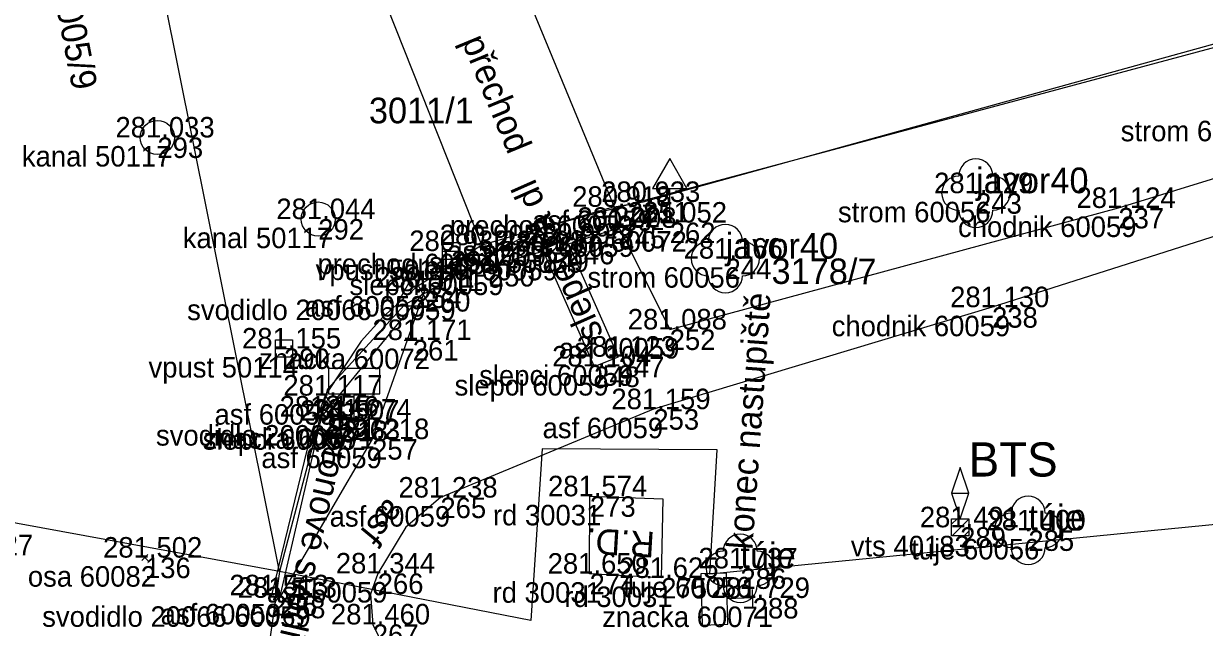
# Model space of a CAD drawing. Extents: x -728659 to -728362, y -1073110 to -1072943.
# Drawn here: x -728508.67 to -728474.14, y -1073039.57 to -1073021.92 of the extents above; entities that cross this region are included whole.
import ezdxf

# ---------------------------------------------------------------- set-up
doc = ezdxf.new("R2010")
doc.units = 0
for name, color, linetype in [('Vrstva 17', 7, 'Continuous'), ('Vrstva 23', 7, 'Continuous'), ('Vrstva 33', 7, 'Continuous'), ('Vrstva 43', 7, 'Continuous'), ('Vrstva 49', 7, 'Continuous'), ('Vrstva 50', 7, 'Continuous'), ('Vrstva 51', 7, 'Continuous'), ('Vrstva 53', 7, 'Continuous'), ('Vrstva 55', 7, 'Continuous'), ('Vrstva 57', 7, 'Continuous'), ('Vrstva 60', 7, 'Continuous'), ('Vrstva 61', 7, 'Continuous'), ('Vrstva 62', 7, 'Continuous'), ('Vrstva 63', 7, 'Continuous')]:
    doc.layers.add(name, color=color, linetype=linetype)

msp = doc.modelspace()

# ---------------------------------------------------------------- linework, layer by layer
at = {"layer": 'Vrstva 17'}
msp.add_lwpolyline([(-728496.944, -1073029.737), (-728499.959, -1073033.406), (-728501.183, -1073038.706)], dxfattribs=at)
at = {"layer": 'Vrstva 23'}
msp.add_lwpolyline([(-728490.023, -1073038.127), (-728492.121, -1073038.002), (-728492.11, -1073035.739), (-728489.978, -1073035.812), (-728490.023, -1073038.127)], dxfattribs=at)
at = {"layer": 'Vrstva 33'}
for p, q in [((-728481.532, -1073035.645), (-728481.032, -1073035.645)), ((-728481.532, -1073036.553), (-728481.374, -1073036.395)), ((-728481.52, -1073036.895), (-728481.032, -1073036.407)), ((-728481.167, -1073036.895), (-728481.032, -1073036.76))]:
    msp.add_line(p, q, dxfattribs=at)
msp.add_lwpolyline([(-728481.282, -1073034.895), (-728481.532, -1073035.645), (-728481.282, -1073036.395), (-728481.032, -1073035.645), (-728481.282, -1073034.895)], dxfattribs=at)
msp.add_lwpolyline([(-728481.532, -1073036.395), (-728481.032, -1073036.395), (-728481.032, -1073036.895), (-728481.532, -1073036.895)], close=True, dxfattribs=at)
at = {"layer": 'Vrstva 43'}
for points in [[(-728496.418, -1073028.566), (-728496.418, -1073028.316), (-728495.918, -1073028.316), (-728495.918, -1073028.816), (-728496.418, -1073028.816), (-728496.418, -1073028.566), (-728495.918, -1073028.566)], [(-728501.306, -1073031.416), (-728501.306, -1073031.166), (-728500.806, -1073031.166), (-728500.806, -1073031.666), (-728501.306, -1073031.666), (-728501.306, -1073031.416), (-728500.806, -1073031.416)]]:
    msp.add_lwpolyline(points, dxfattribs=at)
for centre in [(-728504.759, -1073025.245), (-728500.055, -1073027.632)]:
    msp.add_circle(centre, 0.5, dxfattribs=at)
at = {"layer": 'Vrstva 49'}
for p, q in [((-728505.035, -1073037.62), (-728505.211, -1073037.444)), ((-728505.035, -1073037.444), (-728505.211, -1073037.62))]:
    msp.add_line(p, q, dxfattribs=at)
at = {"layer": 'Vrstva 50'}
for p, q in [((-728480.853, -1073026.875), (-728480.782, -1073026.875)), ((-728488.179, -1073028.788), (-728488.108, -1073028.788)), ((-728479.323, -1073036.736), (-728479.252, -1073036.736)), ((-728487.743, -1073037.847), (-728487.672, -1073037.847))]:
    msp.add_line(p, q, dxfattribs=at)
for centre, start, end in [((-728480.823, -1073026.374), 0, 180), ((-728481.323, -1073026.874), 90, 270), ((-728480.323, -1073026.874), 270, 90), ((-728480.823, -1073027.374), 180, 0), ((-728488.149, -1073028.287), 0, 180), ((-728488.649, -1073028.787), 90, 270), ((-728487.649, -1073028.787), 270, 90), ((-728488.149, -1073029.287), 180, 0), ((-728479.292, -1073036.235), 0, 180), ((-728479.792, -1073036.735), 90, 270), ((-728478.792, -1073036.735), 270, 90), ((-728487.714, -1073037.346), 0, 180), ((-728488.214, -1073037.846), 90, 270), ((-728487.214, -1073037.846), 270, 90), ((-728479.292, -1073037.235), 180, 0), ((-728487.714, -1073038.346), 180, 0)]:
    msp.add_arc(centre, 0.5, start, end, dxfattribs=at)
at = {"layer": 'Vrstva 51'}
for p, q in [((-728490.027, -1073027.735), (-728489.527, -1073027.735)), ((-728497.54, -1073031.169), (-728497.04, -1073031.169)), ((-728499.25, -1073033.497), (-728498.75, -1073033.497)), ((-728487.341, -1073038.963), (-728487.355, -1073038.463))]:
    msp.add_line(p, q, dxfattribs=at)
for points in [[(-728491.401, -1073027.273), (-728490.555, -1073027.131), (-728438.49, -1073012.708)], [(-728491.25, -1073027.888), (-728489.777, -1073030.86), (-728476.655, -1073027.306), (-728450.209, -1073019.139)], [(-728498.56, -1073020.107), (-728494.628, -1073019.466), (-728491.401, -1073027.273), (-728495.275, -1073028.394), (-728498.56, -1073020.107)], [(-728449.745, -1073020.446), (-728480.35, -1073030.208), (-728490.255, -1073033.191), (-728496.482, -1073035.776)], [(-728489.777, -1073027.735), (-728489.777, -1073026.735), (-728489.277, -1073026.735), (-728489.777, -1073025.86), (-728490.277, -1073026.735), (-728489.777, -1073026.735)], [(-728495.275, -1073028.394), (-728495.063, -1073029.004), (-728493.479, -1073028.573), (-728491.99, -1073031.943), (-728491.271, -1073031.657), (-728492.733, -1073028.355), (-728491.25, -1073027.888), (-728491.401, -1073027.273)], [(-728495.275, -1073028.394), (-728497.204, -1073029.633), (-728498.169, -1073030.501), (-728498.796, -1073031.198), (-728499.849, -1073032.794), (-728500.268, -1073033.914), (-728501.425, -1073038.634)], [(-728497.29, -1073031.169), (-728497.29, -1073030.169), (-728496.79, -1073030.169), (-728497.29, -1073029.294), (-728497.79, -1073030.169), (-728497.29, -1073030.169)], [(-728496.944, -1073029.737), (-728498.48, -1073034.066), (-728501.183, -1073038.706)], [(-728499, -1073033.497), (-728499, -1073032.747), (-728498.25, -1073032.747), (-728498.25, -1073031.997), (-728499.75, -1073031.997), (-728499.75, -1073032.747), (-728499, -1073032.747)], [(-728499.849, -1073032.794), (-728499.355, -1073033.527)], [(-728496.482, -1073035.776), (-728497.494, -1073036.644), (-728498.316, -1073037.996), (-728498.528, -1073038.603), (-728498.459, -1073039.486), (-728498.149, -1073040.128), (-728497.533, -1073040.603), (-728496.825, -1073040.892), (-728494.827, -1073041.079), (-728486.835, -1073041.479), (-728486.937, -1073042.858), (-728494.923, -1073042.391), (-728498.977, -1073042.014), (-728499.069, -1073042.727), (-728513.553, -1073040.642)], [(-728487.348, -1073038.713), (-728488.098, -1073038.733), (-728488.118, -1073037.983), (-728488.867, -1073038.003), (-728488.827, -1073039.503), (-728488.078, -1073039.483), (-728488.098, -1073038.733)]]:
    msp.add_lwpolyline(points, dxfattribs=at)
at = {"layer": 'Vrstva 53'}
msp.add_lwpolyline([(-728443.68, -1073014.51), (-728493.68, -1073027.94), (-728497.54, -1073030.15), (-728499.78, -1073032.61), (-728501.19, -1073037.94), (-728503.24, -1073052.34), (-728496.81, -1073052.21), (-728491.97, -1073053.44), (-728477.97, -1073053.19), (-728434.587, -1073049.291), (-728361.73, -1073039.5)], dxfattribs=at)
at = {"layer": 'Vrstva 55'}
for q in [(-728506.11, -1073013.42), (-728510.22, -1073036.28)]:
    msp.add_line((-728501.19, -1073037.94), q, dxfattribs=at)
msp.add_lwpolyline([(-728462.29, -1073035.43), (-728488.6, -1073038.02), (-728488.39, -1073034.38), (-728493.51, -1073034.35), (-728493.84, -1073039.37), (-728501.19, -1073037.94)], dxfattribs=at)
at = {"layer": 'Vrstva 60'}
for p, q in [((-728504.759, -1073025.245), (-728504.759, -1073025.245)), ((-728490.555, -1073027.131), (-728490.555, -1073027.131)), ((-728480.817, -1073026.875), (-728480.817, -1073026.875)), ((-728491.401, -1073027.273), (-728491.401, -1073027.273)), ((-728476.655, -1073027.306), (-728476.655, -1073027.306)), ((-728500.055, -1073027.632), (-728500.055, -1073027.632)), ((-728489.777, -1073027.735), (-728489.777, -1073027.735)), ((-728491.25, -1073027.888), (-728491.25, -1073027.888)), ((-728496.168, -1073028.566), (-728496.168, -1073028.566)), ((-728495.275, -1073028.394), (-728495.275, -1073028.394)), ((-728492.733, -1073028.355), (-728492.733, -1073028.355)), ((-728493.479, -1073028.573), (-728493.479, -1073028.573)), ((-728488.143, -1073028.788), (-728488.143, -1073028.788)), ((-728495.063, -1073029.004), (-728495.063, -1073029.004)), ((-728497.204, -1073029.633), (-728497.204, -1073029.633)), ((-728496.944, -1073029.737), (-728496.944, -1073029.737)), ((-728480.35, -1073030.208), (-728480.35, -1073030.208)), ((-728489.777, -1073030.86), (-728489.777, -1073030.86)), ((-728497.29, -1073031.169), (-728497.29, -1073031.169)), ((-728501.056, -1073031.416), (-728501.056, -1073031.416)), ((-728491.271, -1073031.657), (-728491.271, -1073031.657)), ((-728491.99, -1073031.943), (-728491.99, -1073031.943)), ((-728499.849, -1073032.794), (-728499.849, -1073032.794)), ((-728490.255, -1073033.191), (-728490.255, -1073033.191)), ((-728499.959, -1073033.406), (-728499.959, -1073033.406)), ((-728499.355, -1073033.527), (-728499.355, -1073033.527)), ((-728499, -1073033.497), (-728499, -1073033.497)), ((-728498.48, -1073034.066), (-728498.48, -1073034.066)), ((-728496.482, -1073035.776), (-728496.482, -1073035.776)), ((-728492.11, -1073035.739), (-728492.11, -1073035.739)), ((-728481.282, -1073036.645), (-728481.282, -1073036.645)), ((-728479.287, -1073036.736), (-728479.287, -1073036.736)), ((-728505.123, -1073037.532), (-728505.123, -1073037.532)), ((-728487.708, -1073037.847), (-728487.708, -1073037.847)), ((-728498.316, -1073037.996), (-728498.316, -1073037.996)), ((-728492.121, -1073038.002), (-728492.121, -1073038.002)), ((-728490.023, -1073038.127), (-728490.023, -1073038.127)), ((-728501.425, -1073038.634), (-728501.425, -1073038.634)), ((-728501.183, -1073038.706), (-728501.183, -1073038.706)), ((-728487.348, -1073038.713), (-728487.348, -1073038.713)), ((-728498.459, -1073039.486), (-728498.459, -1073039.486))]:
    msp.add_line(p, q, dxfattribs=at)

# ---------------------------------------------------------------- texts
at = {"layer": 'Vrstva 23'}
msp.add_text('R.D.', height=0.75, rotation=176.5903, dxfattribs=at).set_placement((-728490.194, -1073036.786))
at = {"layer": 'Vrstva 33'}
msp.add_text('BTS', height=1, dxfattribs=at).set_placement((-728481.032, -1073035.161))
at = {"layer": 'Vrstva 51'}
for s, rotation, p in [('přechod', 292.4576, (-728495.874, -1073022.428)), ('slepecká dl ', 113.8819, (-728491.704, -1073031.002)), ('asf', 230.439, (-728498.024, -1073035.754))]:
    msp.add_text(s, height=0.75, rotation=rotation, dxfattribs=at).set_placement(p)
at = {"layer": 'Vrstva 57'}
for s, rotation, p in [('3005/9', 280.9963, (-728507.822, -1073020.889)), ('3178/7', 359.7358, (-728486.799, -1073029.526))]:
    msp.add_text(s, height=0.75, rotation=rotation, dxfattribs=at).set_placement(p)
msp.add_text('3011/1', height=0.75, dxfattribs=at).set_placement((-728498.572, -1073024.831))
at = {"layer": 'Vrstva 60'}
for s, p in [('293', (-728504.759, -1073025.845)), ('251', (-728490.555, -1073027.731)), ('243', (-728480.817, -1073027.475)), ('222', (-728491.401, -1073027.873)), ('237', (-728476.655, -1073027.906)), ('292', (-728500.055, -1073028.232)), ('245', (-728491.25, -1073028.488)), ('262', (-728489.777, -1073028.335)), ('291', (-728496.168, -1073029.166)), ('223', (-728495.275, -1073028.994)), ('249', (-728493.479, -1073029.173)), ('246', (-728492.733, -1073028.955)), ('244', (-728488.143, -1073029.388)), ('250', (-728495.063, -1073029.604)), ('254', (-728497.204, -1073030.233)), ('260', (-728496.944, -1073030.337)), ('238', (-728480.35, -1073030.808)), ('252', (-728489.777, -1073031.46)), ('261', (-728497.29, -1073031.769)), ('290', (-728501.056, -1073032.016)), ('247', (-728491.271, -1073032.257)), ('248', (-728491.99, -1073032.543)), ('255', (-728499.849, -1073033.394)), ('259', (-728499.959, -1073034.006)), ('253', (-728490.255, -1073033.791)), ('218', (-728499.355, -1073034.127)), ('263', (-728499, -1073034.097)), ('257', (-728498.48, -1073034.666)), ('265', (-728496.482, -1073036.376)), ('273', (-728492.11, -1073036.339)), ('289', (-728481.282, -1073037.245)), ('285', (-728479.287, -1073037.336)), ('136', (-728505.123, -1073038.132)), ('286', (-728487.708, -1073038.447)), ('266', (-728498.316, -1073038.596)), ('274', (-728492.121, -1073038.602)), ('275', (-728490.023, -1073038.727)), ('256', (-728501.425, -1073039.234)), ('258', (-728501.183, -1073039.306)), ('288', (-728487.348, -1073039.313)), ('267', (-728498.459, -1073040.086))]:
    msp.add_text(s, height=0.6, dxfattribs=at).set_placement(p)
at = {"layer": 'Vrstva 61'}
for s, p in [('281.033', (-728505.985, -1073025.245)), ('281.129', (-728482.044, -1073026.875)), ('280.918', (-728492.628, -1073027.273)), ('280.933', (-728491.781, -1073027.131)), ('281.124', (-728477.88, -1073027.306)), ('281.044', (-728501.28, -1073027.632)), ('281.052', (-728491.001, -1073027.735)), ('281.008', (-728492.477, -1073027.888)), ('280.905', (-728496.503, -1073028.394)), ('280.995', (-728493.961, -1073028.355)), ('280.932', (-728497.392, -1073028.566)), ('280.987', (-728494.705, -1073028.573)), ('281.166', (-728489.369, -1073028.788)), ('281.009', (-728496.29, -1073029.004)), ('280.971', (-728498.383, -1073029.633)), ('281.011', (-728498.123, -1073029.737)), ('281.130', (-728481.575, -1073030.208)), ('281.088', (-728491.004, -1073030.86)), ('281.171', (-728498.469, -1073031.169)), ('281.155', (-728502.284, -1073031.416)), ('281.104', (-728493.215, -1073031.943)), ('281.123', (-728492.497, -1073031.657)), ('281.117', (-728501.075, -1073032.794)), ('281.159', (-728491.482, -1073033.191)), ('281.146', (-728501.185, -1073033.406)), ('281.507', (-728500.581, -1073033.527)), ('281.274', (-728500.225, -1073033.497)), ('281.218', (-728499.707, -1073034.066)), ('281.574', (-728493.335, -1073035.739)), ('281.238', (-728497.709, -1073035.776)), ('281.491', (-728482.461, -1073036.645)), ('281.400', (-728480.512, -1073036.736)), ('281.627', (-728511.292, -1073037.464)), ('281.502', (-728506.347, -1073037.532)), ('281.344', (-728499.541, -1073037.996)), ('281.650', (-728493.346, -1073038.002)), ('281.625', (-728491.251, -1073038.127)), ('281.737', (-728488.934, -1073037.847)), ('281.513', (-728502.651, -1073038.634)), ('281.513', (-728502.409, -1073038.706)), ('281.729', (-728488.575, -1073038.713)), ('281.460', (-728499.684, -1073039.486))]:
    msp.add_text(s, height=0.6, dxfattribs=at).set_placement(p)
at = {"layer": 'Vrstva 62'}
for s, p in [('strom 60056', (-728476.587, -1073025.356)), ('kanal 50117', (-728508.722, -1073026.095)), ('strom 60056', (-728484.856, -1073027.725)), ('prechod 60059', (-728496.206, -1073028.123)), ('asf 60059', (-728493.794, -1073027.981)), ('chodnik 60059', (-728481.345, -1073028.156)), ('kanal 50117', (-728504.018, -1073028.482)), ('slepci 60059', (-728495.328, -1073028.738)), ('znacka 60072', (-728494.271, -1073028.585)), ('vpust 50114', (-728500.13, -1073029.416)), ('prechod 60059', (-728500.08, -1073029.244)), ('slepci 60059', (-728497.557, -1073029.423)), ('slepci 60059', (-728496.811, -1073029.205)), ('slepci 60059', (-728499.141, -1073029.854)), ('strom 60056', (-728492.182, -1073029.638)), ('asf 60059', (-728500.443, -1073030.483)), ('svodidlo 20066 60059', (-728503.889, -1073030.587)), ('chodnik 60059', (-728485.04, -1073031.058)), ('asf 60059', (-728493.016, -1073031.71)), ('vpust 50114', (-728505.018, -1073032.266)), ('znacka 60072', (-728501.784, -1073032.019)), ('slepci 60059', (-728495.349, -1073032.507)), ('slepci 60059', (-728496.068, -1073032.793)), ('asf 60059', (-728503.088, -1073033.644)), ('svodidlo 20066', (-728504.8, -1073034.256)), ('slepci 60059', (-728503.433, -1073034.377)), ('znacka 60071', (-728503.403, -1073034.347)), ('asf 60059', (-728493.494, -1073034.041)), ('asf 60059', (-728501.719, -1073034.916)), ('asf 60059', (-728499.721, -1073036.626)), ('rd 30031', (-728494.946, -1073036.589)), ('vts 40183', (-728484.481, -1073037.495)), ('tuje 60056', (-728482.715, -1073037.586)), ('osa 60082', (-728508.547, -1073038.382)), ('asf 60059', (-728501.555, -1073038.846)), ('rd 30031', (-728494.957, -1073038.852)), ('tuje 60056', (-728491.136, -1073038.697)), ('rd 30031', (-728492.859, -1073038.977)), ('svodidlo 20066 60059', (-728508.128, -1073039.556)), ('asf 60059', (-728504.664, -1073039.484)), ('znacka 60071', (-728491.751, -1073039.563))]:
    msp.add_text(s, height=0.6, dxfattribs=at).set_placement(p)
at = {"layer": 'Vrstva 63'}
for s, p in [('javor40', (-728480.817, -1073026.875)), ('javor40', (-728488.143, -1073028.788)), ('túje', (-728479.287, -1073036.736)), ('túje', (-728487.708, -1073037.847))]:
    msp.add_text(s, height=0.75, dxfattribs=at).set_placement(p)
for s, rotation, p in [('konec nastupiště', 85.8602, (-728487.36, -1073037.315)), ('betonové svodidlo', 256.9959, (-728499.662, -1073033.23))]:
    msp.add_text(s, height=0.75, rotation=rotation, dxfattribs=at).set_placement(p)

doc.saveas('drawing.dxf')
